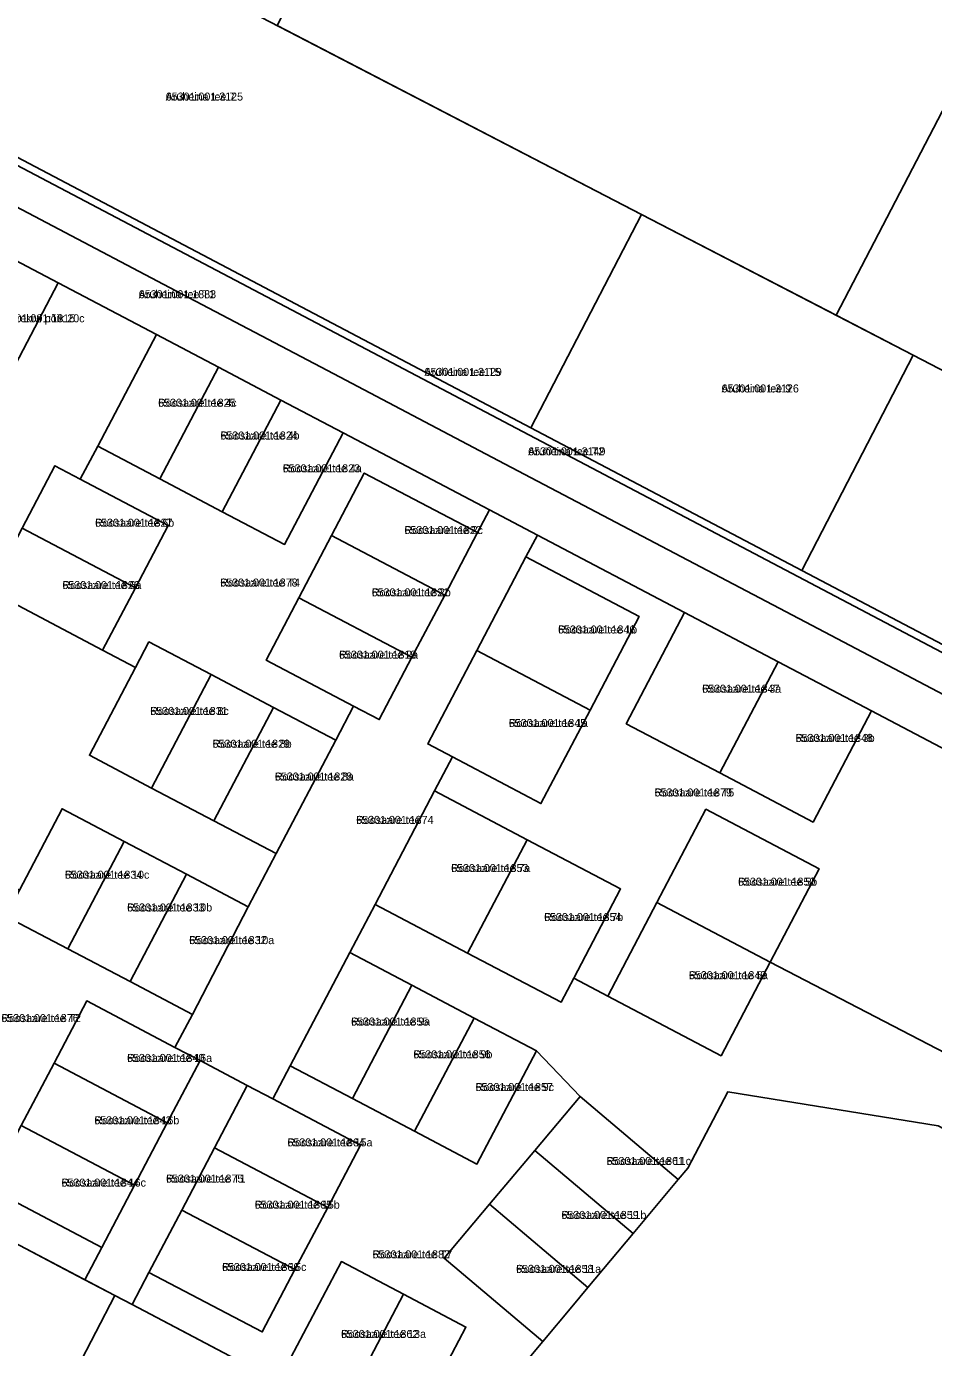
# Model space of a CAD drawing. Extents: x 543236 to 563717, y 6566033 to 6588992.
# Drawn here: x 545877.3 to 546047.5, y 6584851 to 6585098.7 of the extents above; entities that cross this region are included whole.
import ezdxf

# ---------------------------------------------------------------- set-up
doc = ezdxf.new("R2010")
doc.units = 0
for name, color, linetype in [('L_AADRESS', 7, 'Continuous'), ('PIIR', 7, 'Continuous'), ('TUNNUS', 7, 'Continuous')]:
    doc.layers.add(name, color=color, linetype=linetype)

msp = doc.modelspace()

# ---------------------------------------------------------------- linework, layer by layer
at = {"layer": 'PIIR'}
for points in [[(545979.47, 6585188.81), (546077.67, 6585137.67), (546029.23, 6585044.54), (545992.67, 6585063.45), (545924.36, 6585098.85), (545944.99, 6585138.67), (545968.64, 6585184.3), (545975.34, 6585180.84)], [(545833.08, 6585146.15), (545992.67, 6585063.45), (545971.92, 6585023.44), (545833.63, 6585096.27), (545823.69, 6585128.22)], [(546077.67, 6585137.67), (546145.4, 6585102.39), (546155.5, 6585097.14), (546161.32, 6585076.91), (546162.49, 6585047.98), (546147.21, 6584983.35), (546094.34, 6585010.78), (546043.67, 6585037.07), (546029.23, 6585044.54)], [(545812.07, 6585106.08), (545823.69, 6585128.22), (545833.63, 6585096.27), (545971.92, 6585023.44), (546022.77, 6584996.72), (546073.26, 6584970.13), (546133.17, 6584938.54), (546131.11, 6584938.14)], [(545805.7, 6585107.83), (545811.43, 6585104.81), (545812.07, 6585106.08), (546131.11, 6584938.14), (546133.17, 6584938.54), (546136.79, 6584939.31), (546134.3, 6584928.75), (546078.99, 6584957.84), (546025.89, 6584985.76), (545964.63, 6585017.97), (545933.81, 6585034.18), (545906.53, 6585048.53), (545879.98, 6585062.49), (545851.77, 6585077.33), (545826.71, 6585090.51), (545821.39, 6585093.3), (545808.87, 6585099.89), (545803.14, 6585102.9)], [(545992.67, 6585063.45), (546043.67, 6585037.07), (546022.77, 6584996.72), (545971.92, 6585023.44)], [(545871.59, 6585056.76), (545883.28, 6585050.61), (545872.28, 6585029.7), (545860.6, 6585035.84)], [(545901.69, 6585040.93), (545913.37, 6585034.79), (545902.37, 6585013.87), (545890.69, 6585020.02)], [(546043.67, 6585037.07), (546094.34, 6585010.78), (546073.26, 6584970.13), (546022.77, 6584996.72)], [(545913.37, 6585034.79), (545925.05, 6585028.64), (545914.05, 6585007.73), (545902.37, 6585013.87)], [(545925.05, 6585028.64), (545936.73, 6585022.5), (545925.74, 6585001.58), (545914.05, 6585007.73)], [(545890.69, 6585020.02), (545902.37, 6585013.87), (545914.05, 6585007.73), (545925.74, 6585001.58), (545936.73, 6585022.5), (545964.17, 6585008.07), (545961.93, 6585003.8), (545940.69, 6585014.97), (545934.54, 6585003.29), (545928.4, 6584991.6), (545922.26, 6584979.92), (545938.7, 6584971.27), (545935.35, 6584964.89), (545923.67, 6584971.03), (545911.98, 6584977.18), (545900.3, 6584983.32), (545897.79, 6584978.55), (545891.61, 6584981.8), (545897.75, 6584993.48), (545903.89, 6585005.16), (545887.43, 6585013.82)], [(545882.65, 6585016.34), (545887.43, 6585013.82), (545903.89, 6585005.16), (545897.75, 6584993.48), (545876.51, 6585004.65)], [(545940.69, 6585014.97), (545961.93, 6585003.8), (545955.78, 6584992.11), (545934.54, 6585003.29)], [(545964.17, 6585008.07), (545973.17, 6585003.34), (545971.02, 6584999.25), (545961.8, 6584981.72), (545952.59, 6584964.2), (545957.24, 6584961.75), (545953.89, 6584955.38), (545942.71, 6584934.12), (545937.97, 6584925.1), (545926.8, 6584903.85), (545923.54, 6584897.66), (545918.73, 6584900.19), (545909.88, 6584904.84), (545905.18, 6584907.31), (545908.44, 6584913.51), (545918.94, 6584933.69), (545924.18, 6584943.64), (545935.35, 6584964.89), (545938.7, 6584971.27), (545943.5, 6584968.75), (545949.64, 6584980.43), (545955.78, 6584992.11), (545961.93, 6585003.8)], [(545876.51, 6585004.65), (545897.75, 6584993.48), (545891.61, 6584981.8), (545870.37, 6584992.97)], [(545934.54, 6585003.29), (545955.78, 6584992.11), (545949.64, 6584980.43), (545928.4, 6584991.6)], [(545973.17, 6585003.34), (546000.79, 6584988.82), (545989.83, 6584967.98), (546007.36, 6584958.77), (546024.88, 6584949.55), (546035.84, 6584970.39), (546074.81, 6584949.89), (546051.4, 6584905.35), (546016.83, 6584923.27), (546026.04, 6584940.78), (546004.78, 6584951.96), (545995.57, 6584934.45), (545986.36, 6584916.93), (545979.98, 6584920.28), (545988.78, 6584937.02), (545971.26, 6584946.24), (545953.89, 6584955.38), (545957.24, 6584961.75), (545973.83, 6584953.02), (545983.04, 6584970.55), (545992.26, 6584988.07), (545971.02, 6584999.25)], [(545971.02, 6584999.25), (545992.26, 6584988.07), (545983.04, 6584970.55), (545961.8, 6584981.72)], [(545928.4, 6584991.6), (545949.64, 6584980.43), (545943.5, 6584968.75), (545938.7, 6584971.27), (545922.26, 6584979.92)], [(546000.79, 6584988.82), (546018.31, 6584979.6), (546007.36, 6584958.77), (545989.83, 6584967.98)], [(545900.3, 6584983.32), (545911.98, 6584977.18), (545900.81, 6584955.93), (545889.13, 6584962.08), (545897.79, 6584978.55)], [(545961.8, 6584981.72), (545983.04, 6584970.55), (545973.83, 6584953.02), (545957.24, 6584961.75), (545952.59, 6584964.2)], [(545911.98, 6584977.18), (545923.67, 6584971.03), (545912.49, 6584949.79), (545900.81, 6584955.93)], [(546018.31, 6584979.6), (546035.84, 6584970.39), (546024.88, 6584949.55), (546007.36, 6584958.77)], [(545923.67, 6584971.03), (545935.35, 6584964.89), (545924.18, 6584943.64), (545912.49, 6584949.79)], [(545953.89, 6584955.38), (545971.26, 6584946.24), (545960.08, 6584924.98), (545942.71, 6584934.12)], [(545884.01, 6584952.05), (545895.66, 6584945.93), (545885.07, 6584925.8), (545873.42, 6584931.93), (545875.99, 6584936.81)], [(546004.78, 6584951.96), (546026.04, 6584940.78), (546016.83, 6584923.27), (545995.57, 6584934.45)], [(545895.66, 6584945.93), (545907.34, 6584939.78), (545896.76, 6584919.65), (545885.07, 6584925.8)], [(545971.26, 6584946.24), (545988.78, 6584937.02), (545979.98, 6584920.28), (545977.61, 6584915.76), (545960.08, 6584924.98)], [(545840.18, 6584926.03), (545857.49, 6584916.93), (545863.63, 6584928.61), (545869.69, 6584940.12), (545875.99, 6584936.81), (545873.42, 6584931.93), (545885.07, 6584925.8), (545896.76, 6584919.65), (545908.44, 6584913.51), (545905.18, 6584907.31), (545888.64, 6584916.01), (545882.5, 6584904.33), (545876.35, 6584892.65), (545870.21, 6584880.96), (545891.45, 6584869.79), (545888.28, 6584863.76), (545884.56, 6584865.71), (545860.07, 6584878.59), (545871.9, 6584901.09), (545860.15, 6584907.27), (545848.46, 6584913.42), (545836.78, 6584919.56)], [(545907.34, 6584939.78), (545918.94, 6584933.69), (545908.44, 6584913.51), (545896.76, 6584919.65)], [(545942.71, 6584934.12), (545960.08, 6584924.98), (545977.61, 6584915.76), (545979.98, 6584920.28), (545986.36, 6584916.93), (546007.62, 6584905.75), (546016.83, 6584923.27), (546051.4, 6584905.35), (546120.19, 6584869.49), (546117.08, 6584856.45), (546048.37, 6584892.59), (546008.87, 6584898.97), (546001.36, 6584884.67), (545999.6, 6584882.56), (545981.16, 6584898.09), (545972.99, 6584906.68), (545961.31, 6584912.82), (545949.62, 6584918.97), (545937.97, 6584925.1)], [(545995.57, 6584934.45), (546016.83, 6584923.27), (546007.62, 6584905.75), (545986.36, 6584916.93)], [(545937.97, 6584925.1), (545949.62, 6584918.97), (545938.46, 6584897.72), (545926.8, 6584903.85)], [(545949.62, 6584918.97), (545961.31, 6584912.82), (545950.14, 6584891.58), (545938.46, 6584897.72)], [(545888.64, 6584916.01), (545905.18, 6584907.31), (545909.88, 6584904.84), (545903.74, 6584893.16), (545882.5, 6584904.33)], [(545961.31, 6584912.82), (545972.99, 6584906.68), (545961.81, 6584885.44), (545950.14, 6584891.58)], [(545926.8, 6584903.85), (545938.46, 6584897.72), (545950.14, 6584891.58), (545961.81, 6584885.44), (545972.99, 6584906.68), (545981.16, 6584898.09), (545972.66, 6584888), (545964.16, 6584877.9), (545955.66, 6584867.8), (545974.18, 6584852.2), (545954.65, 6584828.85), (545947.93, 6584832.39), (545959.76, 6584854.88), (545948.08, 6584861.03), (545936.4, 6584867.17), (545924.57, 6584844.67), (545907.57, 6584853.61), (545897.13, 6584859.1), (545900.3, 6584865.14), (545921.55, 6584853.97), (545927.69, 6584865.65), (545933.83, 6584877.33), (545939.97, 6584889.01), (545923.54, 6584897.66)], [(545882.5, 6584904.33), (545903.74, 6584893.16), (545897.59, 6584881.48), (545876.35, 6584892.65)], [(545909.88, 6584904.84), (545918.73, 6584900.19), (545912.59, 6584888.51), (545906.45, 6584876.82), (545900.3, 6584865.14), (545897.13, 6584859.1), (545893.9, 6584860.8), (545888.28, 6584863.76), (545891.45, 6584869.79), (545897.59, 6584881.48), (545903.74, 6584893.16)], [(545918.73, 6584900.19), (545923.54, 6584897.66), (545939.97, 6584889.01), (545933.83, 6584877.33), (545912.59, 6584888.51)], [(546008.87, 6584898.97), (546048.37, 6584892.59), (546117.08, 6584856.45), (546093.16, 6584756.02), (545999.67, 6584805.18), (545954.65, 6584828.85), (545974.18, 6584852.2), (545979.6, 6584858.67), (545982.65, 6584862.32), (545991.13, 6584872.44), (545999.6, 6584882.56), (546001.36, 6584884.67)], [(545981.16, 6584898.09), (545999.6, 6584882.56), (545991.13, 6584872.44), (545972.66, 6584888)], [(545876.35, 6584892.65), (545897.59, 6584881.48), (545891.45, 6584869.79), (545870.21, 6584880.96)], [(545912.59, 6584888.51), (545933.83, 6584877.33), (545927.69, 6584865.65), (545906.45, 6584876.82)], [(545972.66, 6584888), (545991.13, 6584872.44), (545982.65, 6584862.32), (545964.16, 6584877.9)], [(545846.1, 6584885.93), (545893.9, 6584860.8), (545879.63, 6584833.3), (545847.67, 6584849.89), (545831.75, 6584858.15)], [(545906.45, 6584876.82), (545927.69, 6584865.65), (545921.55, 6584853.97), (545900.3, 6584865.14)], [(545964.16, 6584877.9), (545982.65, 6584862.32), (545979.6, 6584858.67), (545974.18, 6584852.2), (545955.66, 6584867.8)], [(545936.4, 6584867.17), (545948.08, 6584861.03), (545936.25, 6584838.53), (545934.12, 6584839.65), (545924.57, 6584844.67)], [(545893.9, 6584860.8), (545897.13, 6584859.1), (545924.57, 6584844.67), (545936.25, 6584838.53), (545945.11, 6584833.87), (545935.03, 6584803.34), (545924.02, 6584803.79), (545877.32, 6584828.86), (545879.63, 6584833.3)], [(545948.08, 6584861.03), (545959.76, 6584854.88), (545947.93, 6584832.39), (545945.11, 6584833.87), (545936.25, 6584838.53)]]:
    msp.add_lwpolyline(points, close=True, dxfattribs=at)
for points in [[(546074.81, 6584949.89), (546035.84, 6584970.39), (546018.31, 6584979.6), (546000.79, 6584988.82), (545973.17, 6585003.34), (545964.17, 6585008.07), (545936.73, 6585022.5), (545925.05, 6585028.64), (545913.37, 6585034.79), (545901.69, 6585040.93), (545883.28, 6585050.61), (545871.59, 6585056.76), (545859.91, 6585062.9), (545848.23, 6585069.05), (545820.99, 6585083.38), (545791.29, 6585101.79)], [(545808.87, 6585099.89), (545821.39, 6585093.3), (545826.71, 6585090.51), (545851.77, 6585077.33), (545879.98, 6585062.49), (545906.53, 6585048.53), (545933.81, 6585034.18), (545964.63, 6585017.97), (546025.89, 6584985.76), (546078.99, 6584957.84)], [(545872.28, 6585029.7), (545883.28, 6585050.61), (545901.69, 6585040.93), (545890.69, 6585020.02), (545887.43, 6585013.82), (545882.65, 6585016.34), (545876.51, 6585004.65)], [(545870.37, 6584992.97), (545891.61, 6584981.8), (545897.79, 6584978.55), (545889.13, 6584962.08), (545900.81, 6584955.93), (545912.49, 6584949.79), (545924.18, 6584943.64), (545918.94, 6584933.69), (545907.34, 6584939.78), (545895.66, 6584945.93), (545884.01, 6584952.05), (545875.99, 6584936.81)]]:
    msp.add_lwpolyline(points, dxfattribs=at)

# ---------------------------------------------------------------- texts
at = {"layer": 'L_AADRESS'}
for s, p in [('Aruheina tee 7', (545903.45, 6585084.79)), ('Aruheina tee T1', (545898.39, 6585047.74)), ('Suurekivi põik 20c', (545871.94, 6585043.23)), ('Aruheina tee T5', (545951.99, 6585033.18)), ('Aruheina tee 9', (546007.71, 6585030.08)), ('Roosaare tee 4c', (545902.03, 6585027.4)), ('Roosaare tee 4b', (545913.71, 6585021.26)), ('Aruheina tee T2', (545971.43, 6585018.29)), ('Roosaare tee 4a', (545925.39, 6585015.11)), ('Roosaare tee 6b', (545890.2, 6585004.91)), ('Roosaare tee 2c', (545948.23, 6585003.54)), ('Roosaare tee 6a', (545884.06, 6584993.23)), ('Roosaare tee T4', (545913.68, 6584993.7)), ('Roosaare tee 2b', (545942.09, 6584991.86)), ('Roosaare tee 1b', (545977.03, 6584984.9)), ('Roosaare tee 2a', (545935.95, 6584980.18)), ('Roosaare tee 3a', (546004.07, 6584973.8)), ('Roosaare tee 8c', (545900.55, 6584969.63)), ('Roosaare tee 1a', (545967.81, 6584967.37)), ('Roosaare tee 8b', (545912.24, 6584963.48)), ('Roosaare tee 3b', (546021.6, 6584964.57)), ('Roosaare tee 8a', (545923.92, 6584957.34)), ('Roosaare tee T5', (545995.15, 6584954.35)), ('Roosaare tee', (545939.18, 6584949.21)), ('Roosaare tee 10c', (545884.54, 6584938.93)), ('Roosaare tee 7a', (545956.98, 6584940.18)), ('Roosaare tee 5b', (546010.8, 6584937.62)), ('Roosaare tee 10b', (545896.21, 6584932.79)), ('Roosaare tee 7b', (545974.43, 6584931)), ('Roosaare tee 10a', (545907.85, 6584926.67)), ('Roosaare tee 5a', (546001.59, 6584920.1)), ('Roosaare tee T2', (545872.61, 6584912.06)), ('Roosaare tee 9a', (545938.21, 6584911.41)), ('Roosaare tee 16a', (545896.19, 6584904.59)), ('Roosaare tee 9b', (545949.89, 6584905.27)), ('Roosaare tee 9c', (545961.57, 6584899.13)), ('Roosaare tee 16b', (545890.05, 6584892.9)), ('Roosaare tee 15a', (545926.28, 6584888.76)), ('Roosaare tee 11c', (545986.15, 6584885.27)), ('Roosaare tee T1', (545903.5, 6584881.97)), ('Roosaare tee 16c', (545883.9, 6584881.22)), ('Roosaare tee 15b', (545920.14, 6584877.08)), ('Roosaare tee 11b', (545977.66, 6584875.16)), ('Roosaare tee T7', (545942.25, 6584867.77)), ('Roosaare tee 15c', (545914, 6584865.4)), ('Roosaare tee 11a', (545969.17, 6584865.05)), ('Roosaare tee 13a', (545936.32, 6584852.85))]:
    msp.add_text(s, height=1.5, dxfattribs=at).set_placement(p)
at = {"layer": 'TUNNUS'}
for s, p in [('65301:001:3125', (545903.45, 6585084.79)), ('65301:001:1883', (545898.39, 6585047.74)), ('65301:001:1815', (545871.94, 6585043.23)), ('65301:001:3129', (545951.99, 6585033.18)), ('65301:001:3126', (546007.71, 6585030.08)), ('65301:001:1825', (545902.03, 6585027.4)), ('65301:001:1824', (545913.71, 6585021.26)), ('65301:001:3149', (545971.43, 6585018.29)), ('65301:001:1823', (545925.39, 6585015.11)), ('65301:001:1827', (545890.2, 6585004.91)), ('65301:001:1822', (545948.23, 6585003.54)), ('65301:001:1826', (545884.06, 6584993.23)), ('65301:001:1878', (545913.68, 6584993.7)), ('65301:001:1821', (545942.09, 6584991.86)), ('65301:001:1846', (545977.03, 6584984.9)), ('65301:001:1819', (545935.95, 6584980.18)), ('65301:001:1847', (546004.07, 6584973.8)), ('65301:001:1831', (545900.55, 6584969.63)), ('65301:001:1845', (545967.81, 6584967.37)), ('65301:001:1829', (545912.24, 6584963.48)), ('65301:001:1848', (546021.6, 6584964.57)), ('65301:001:1828', (545923.92, 6584957.34)), ('65301:001:1879', (545995.15, 6584954.35)), ('65301:001:1874', (545939.18, 6584949.21)), ('65301:001:1834', (545884.54, 6584938.93)), ('65301:001:1853', (545956.98, 6584940.18)), ('65301:001:1850', (546010.8, 6584937.62)), ('65301:001:1833', (545896.21, 6584932.79)), ('65301:001:1854', (545974.43, 6584931)), ('65301:001:1832', (545907.85, 6584926.67)), ('65301:001:1849', (546001.59, 6584920.1)), ('65301:001:1876', (545872.61, 6584912.06)), ('65301:001:1855', (545938.21, 6584911.41)), ('65301:001:1840', (545896.19, 6584904.59)), ('65301:001:1856', (545949.89, 6584905.27)), ('65301:001:1857', (545961.57, 6584899.13)), ('65301:001:1843', (545890.05, 6584892.9)), ('65301:001:1864', (545926.28, 6584888.76)), ('65301:001:1861', (545986.15, 6584885.27)), ('65301:001:1875', (545903.5, 6584881.97)), ('65301:001:1844', (545883.9, 6584881.22)), ('65301:001:1865', (545920.14, 6584877.08)), ('65301:001:1859', (545977.66, 6584875.16)), ('65301:001:1882', (545942.25, 6584867.77)), ('65301:001:1866', (545914, 6584865.4)), ('65301:001:1858', (545969.17, 6584865.05)), ('65301:001:1862', (545936.32, 6584852.85))]:
    msp.add_text(s, height=1.5, dxfattribs=at).set_placement(p)

doc.saveas('drawing.dxf')
